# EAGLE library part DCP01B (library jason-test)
+/- V unregulated DC/DC converter Single supply version - Pin 7 is NC
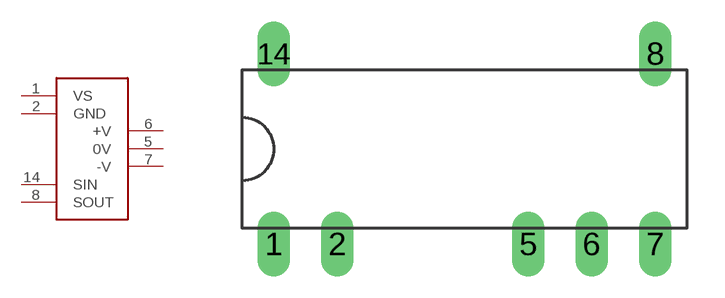
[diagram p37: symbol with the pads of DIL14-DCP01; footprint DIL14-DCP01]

Designator prefix -

## DCP01B  [DIL14-DCP01]
1  VS  in
2  GND  in
5  0V  out
6  +V  out
7  -V  out
8  SOUT  out
14  SIN  in

## Footprint DIL14-DCP01 (pad centres in mm)
drill 0.8 long: 1 -7.62,-3.81; 2 -5.08,-3.81; 5 2.54,-3.81; 6 5.08,-3.81; 7 7.62,-3.81; 8 7.62,3.81; 14 -7.62,3.81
